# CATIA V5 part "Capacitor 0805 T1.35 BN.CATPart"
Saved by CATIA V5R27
Part number: Capacitor 0805 T1.35 BN
Definition: Capacitor 0805 T1.35 BN
Nomenclature: Capacitor 0805 T1.35 BN v3
Source: Unknown
Bounding box of the stored display mesh (mm): x -1.05 to 1.05, y -0.675 to 0.675, z 0 to 1.35
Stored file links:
  E:\university\my-thesis\My Thesis Publication\Final-Updata\CAD\Capacitor 0805 T1.35 BN.CATPart
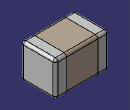
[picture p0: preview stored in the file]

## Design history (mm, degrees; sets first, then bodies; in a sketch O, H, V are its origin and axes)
Body1 "Body1" (main body)
  Solid1: solid without history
